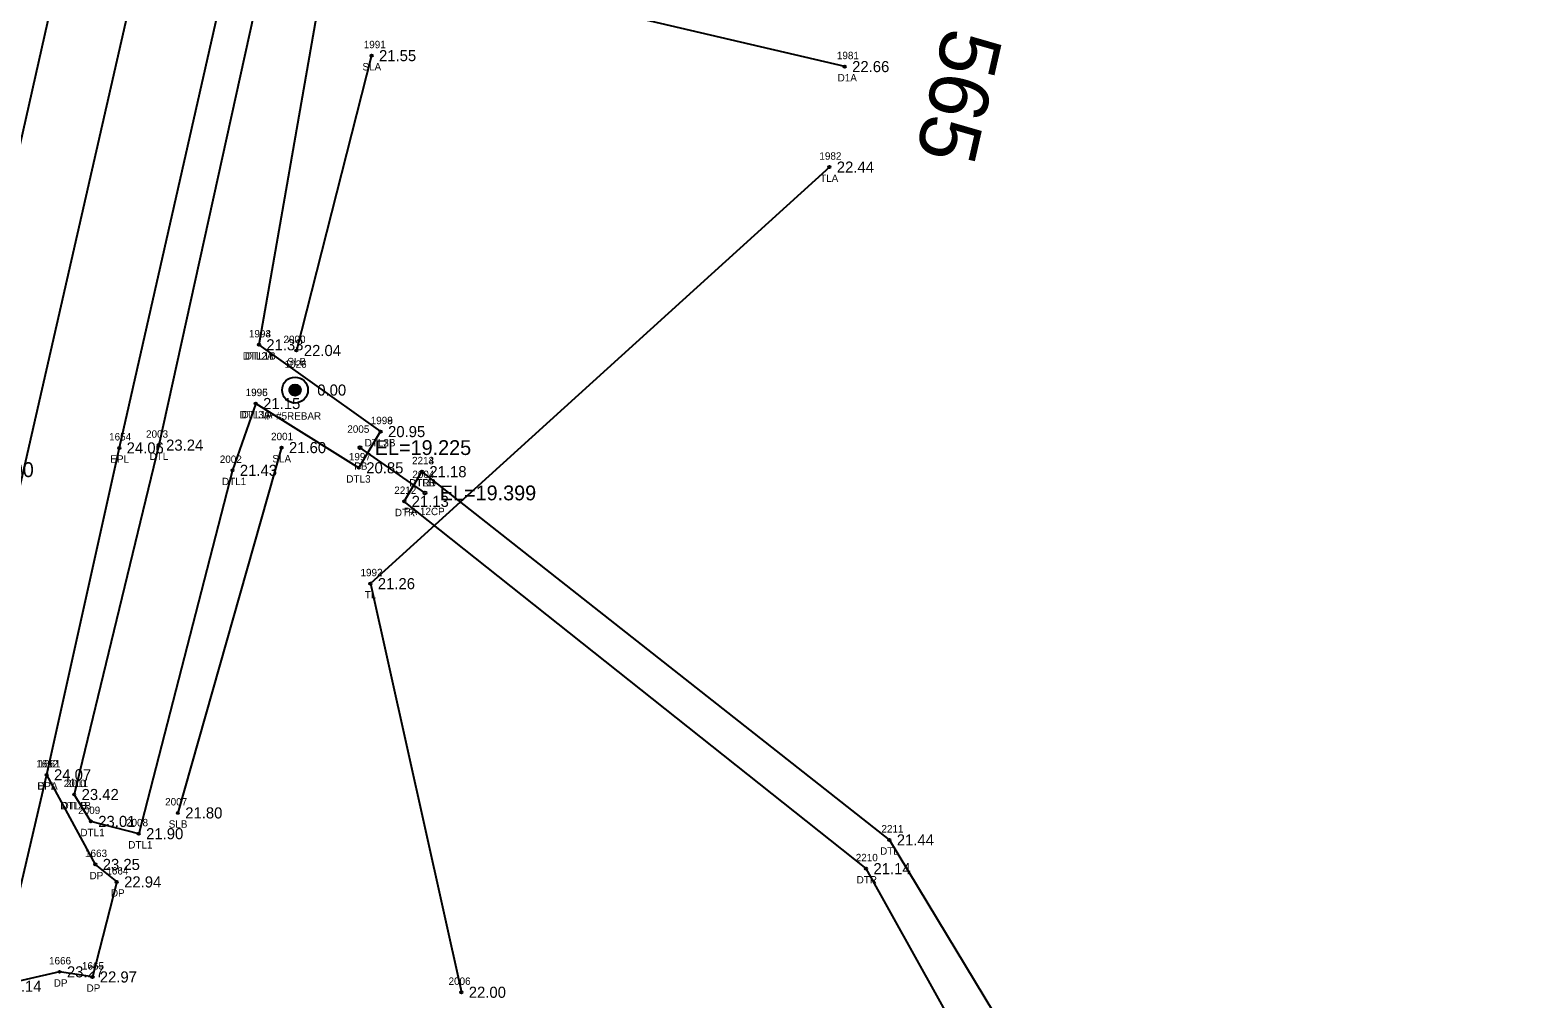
# Model space of a CAD drawing. Extents: x 2654414 to 2656963, y 761776 to 764965.
# Drawn here: x 2655506 to 2655709.5, y 762249.9 to 762380.7 of the extents above; entities that cross this region are included whole.
import ezdxf

# ---------------------------------------------------------------- set-up
doc = ezdxf.new("R2010")
doc.units = 0
for name, color, linetype in [('Default', 7, 'Continuous'), ('RD_EX_DR_Pipe', 7, 'Continuous'), ('RD_EX_DR_Pipe_txCode', 7, 'Continuous'), ('RD_EX_Driveway', 7, 'Continuous'), ('RD_EX_Driveway_txCode', 7, 'Continuous'), ('RD_EX_DV_Prop_txCode', 7, 'Continuous'), ('RD_EX_DV_PropPin', 7, 'Continuous'), ('RD_EX_H2O', 7, 'Continuous'), ('RD_EX_H2O_txCode', 7, 'Continuous'), ('RD_EX_Road', 7, 'Continuous'), ('RD_EX_Road_txCode', 7, 'Continuous'), ('RD_EX_TX_Driveway_ELEV', 7, 'Continuous'), ('RD_EX_TX_DV_Prop_ELEV', 7, 'Continuous'), ('RD_EX_TX_H2O_ELEV', 7, 'Continuous'), ('RD_EX_TX_Road_ELEV', 7, 'Continuous'), ('RD_EX_TX_VEG_ELEV', 7, 'Continuous'), ('RD_EX_VEG', 7, 'Continuous'), ('RD_EX_VEG_txCode', 7, 'Continuous'), ('RD_HC_Cl', 7, 'Continuous'), ('RD_HC_TX_Sta50', 7, 'Continuous'), ('RD_SMD_Locator', 7, 'Continuous'), ('RD_TX_Pipe_ElevEX', 7, 'Continuous')]:
    doc.layers.add(name, color=color, linetype=linetype)

msp = doc.modelspace()

# ---------------------------------------------------------------- linework, layer by layer
at = {"layer": 'Default'}
msp.add_line((2656050.51, 764712.37), (2655383.26, 761787.51), dxfattribs=at)
at = {"layer": 'RD_EX_DR_Pipe'}
msp.add_line((2655559.27, 762318.21), (2655550.49, 762324.33), dxfattribs=at)
at = {"layer": 'RD_EX_Driveway'}
for points in [[(2655615.95, 762375.77), (2655557.51, 762389.46), (2655538.99, 762389.2)], [(2655508.17, 762280.15), (2655514.75, 762268.05), (2655517.64, 762265.69), (2655514.35, 762252.86), (2655509.92, 762253.55), (2655501.46, 762251.6)]]:
    msp.add_lwpolyline(points, dxfattribs=at)
at = {"layer": 'RD_EX_DV_PropPin'}
for p, q in [((2655541.16, 762331.59), (2655541.16, 762332.62)), ((2655541.19, 762331.55), (2655541.19, 762332.65)), ((2655541.23, 762331.52), (2655541.23, 762332.68)), ((2655541.26, 762331.49), (2655541.26, 762332.71)), ((2655541.3, 762331.47), (2655541.3, 762332.73)), ((2655541.33, 762331.44), (2655541.33, 762332.76)), ((2655541.37, 762331.42), (2655541.37, 762332.78)), ((2655541.4, 762331.41), (2655541.4, 762332.79)), ((2655541.44, 762331.39), (2655541.44, 762332.81)), ((2655541.47, 762331.38), (2655541.47, 762332.82)), ((2655541.51, 762331.37), (2655541.51, 762332.83)), ((2655541.54, 762331.36), (2655541.54, 762332.84)), ((2655541.58, 762331.35), (2655541.58, 762332.85)), ((2655541.61, 762331.35), (2655541.61, 762332.85)), ((2655541.65, 762331.34), (2655541.65, 762332.86)), ((2655541.68, 762331.34), (2655541.68, 762332.86)), ((2655541.72, 762331.34), (2655541.72, 762332.86)), ((2655541.75, 762331.34), (2655541.75, 762332.86)), ((2655541.79, 762331.34), (2655541.79, 762332.86)), ((2655541.82, 762331.35), (2655541.82, 762332.85)), ((2655541.86, 762331.35), (2655541.86, 762332.85)), ((2655541.89, 762331.36), (2655541.89, 762332.84)), ((2655541.93, 762331.37), (2655541.93, 762332.83)), ((2655541.96, 762331.38), (2655541.96, 762332.82)), ((2655542, 762331.39), (2655542, 762332.81)), ((2655542.03, 762331.41), (2655542.03, 762332.79)), ((2655542.07, 762331.42), (2655542.07, 762332.78)), ((2655542.1, 762331.44), (2655542.1, 762332.76)), ((2655542.14, 762331.47), (2655542.14, 762332.73)), ((2655542.17, 762331.49), (2655542.17, 762332.71)), ((2655542.21, 762331.52), (2655542.21, 762332.68)), ((2655542.24, 762331.55), (2655542.24, 762332.65)), ((2655542.28, 762331.59), (2655542.28, 762332.62)), ((2655540.98, 762331.9), (2655540.98, 762332.3)), ((2655541.02, 762331.8), (2655541.02, 762332.4)), ((2655541.05, 762331.73), (2655541.05, 762332.47)), ((2655541.09, 762331.67), (2655541.09, 762332.53)), ((2655541.12, 762331.63), (2655541.12, 762332.57)), ((2655542.32, 762331.63), (2655542.32, 762332.57)), ((2655542.35, 762331.67), (2655542.35, 762332.53)), ((2655542.39, 762331.73), (2655542.39, 762332.47)), ((2655542.42, 762331.8), (2655542.42, 762332.4)), ((2655542.46, 762331.9), (2655542.46, 762332.3))]:
    msp.add_line(p, q, dxfattribs=at)
for radius in [1.75, 0.761]:
    msp.add_circle((2655541.72, 762332.1), radius, dxfattribs=at)
at = {"layer": 'RD_EX_H2O'}
for p, q in [((2655545.09, 762385.45), (2655536.84, 762338.21)), ((2655536.84, 762338.21), (2655553.28, 762326.49))]:
    msp.add_line(p, q, dxfattribs=at)
for points in [[(2655545.09, 762385.45), (2655540, 762387.21), (2655536.16, 762382.83), (2655523.31, 762324.66), (2655511.9, 762277.49)], [(2655536.41, 762330.28), (2655533.27, 762321.26), (2655520.61, 762272.2), (2655514.15, 762273.86), (2655511.9, 762277.49)], [(2655536.41, 762330.28), (2655550.34, 762321.6), (2655553.28, 762326.49)], [(2655458.25, 762004.65), (2655489.16, 762003.6), (2655538.42, 762005.59), (2655556.05, 762013.17), (2655587.88, 762051.39), (2655643.4, 762074.04), (2655655.85, 762091.76), (2655681.86, 762140.14), (2655683.72, 762146.53), (2655664.39, 762201.23), (2655621.98, 762271.36), (2655558.86, 762321.08)], [(2655459.71, 762010.57), (2655488.92, 762008.22), (2655537.08, 762011.25), (2655554.9, 762018.55), (2655583.72, 762054.68), (2655639.44, 762078.76), (2655651.66, 762094.07), (2655673.82, 762140.27), (2655676.22, 762150.22), (2655658.16, 762196.88), (2655618.83, 762267.48), (2655556.47, 762317.07), (2655558.86, 762321.08)]]:
    msp.add_lwpolyline(points, dxfattribs=at)
at = {"layer": 'RD_EX_Road'}
for points in [[(2655700.99, 763232.28), (2655693.55, 763198.57), (2655671.65, 763102.04), (2655649.04, 763001.06), (2655627.27, 762906.23), (2655605, 762809.37), (2655598.99, 762783.09), (2655583.65, 762714.14), (2655561.97, 762618.32), (2655556.36, 762593.84), (2655548.11, 762557.14), (2655540.1, 762522.48), (2655518.03, 762425.04), (2655496.48, 762329.56), (2655475.55, 762236.62), (2655473.2, 762226.14), (2655466.57, 762197.5), (2655460.06, 762168.16), (2655454.26, 762143.78), (2655432.5, 762049.88), (2655410.7, 761955.51), (2655388.17, 761858.43), (2655373.5, 761793.95)], [(2655670.04, 762995.18), (2655648.57, 762900.67), (2655631.27, 762824.03), (2655626.67, 762802.87), (2655621.78, 762781.91), (2655611.71, 762738.43), (2655604.93, 762708.62), (2655582.64, 762610.54), (2655576.46, 762583.32), (2655561.41, 762517.24), (2655539.15, 762414.81), (2655531.98, 762386.15), (2655517.98, 762324.29), (2655508.17, 762280.15), (2655501.46, 762251.6), (2655496.92, 762232.09), (2655477.2, 762144.97), (2655472.14, 762122.52), (2655453.74, 762045.1), (2655431.79, 761949.92), (2655409.76, 761853.25), (2655401.25, 761816.42), (2655394.61, 761787.37)]]:
    msp.add_lwpolyline(points, dxfattribs=at)
at = {"layer": 'RD_EX_VEG'}
for p, q in [((2655552.06, 762377.25), (2655541.91, 762337.44)), ((2655539.9, 762324.33), (2655525.89, 762275.01))]:
    msp.add_line(p, q, dxfattribs=at)
msp.add_lwpolyline([(2655613.88, 762362.2), (2655551.9, 762305.96), (2655564.18, 762250.79)], dxfattribs=at)
at = {"layer": 'RD_HC_Cl'}
msp.add_line((2656050.51, 764712.37), (2655383.26, 761787.51), dxfattribs=at)
at = {"layer": 'RD_SMD_Locator'}
for centre, radius in [((2655552.06, 762377.25), 0.15), ((2655615.95, 762375.77), 0.15), ((2655613.88, 762362.2), 0.15), ((2655536.84, 762338.21), 0.15), ((2655536.84, 762338.21), 0.15), ((2655541.91, 762337.44), 0.15), ((2655541.72, 762332.1), 0.15), ((2655536.41, 762330.28), 0.15), ((2655536.41, 762330.28), 0.15), ((2655553.28, 762326.49), 0.15), ((2655553.28, 762326.49), 0.15), ((2655523.31, 762324.66), 0.15), ((2655539.9, 762324.33), 0.15), ((2655550.49, 762324.33), 0.2), ((2655517.98, 762324.29), 0.15), ((2655533.27, 762321.26), 0.15), ((2655550.34, 762321.6), 0.15), ((2655558.86, 762321.08), 0.15), ((2655558.86, 762321.08), 0.15), ((2655559.27, 762318.21), 0.2), ((2655556.47, 762317.07), 0.15), ((2655551.9, 762305.96), 0.15), ((2655508.17, 762280.15), 0.15), ((2655508.17, 762280.15), 0.15), ((2655511.9, 762277.49), 0.15), ((2655511.9, 762277.49), 0.15), ((2655514.15, 762273.86), 0.15), ((2655525.89, 762275.01), 0.15), ((2655520.61, 762272.2), 0.15), ((2655621.98, 762271.36), 0.15), ((2655514.75, 762268.05), 0.15), ((2655618.83, 762267.48), 0.15), ((2655517.64, 762265.69), 0.15), ((2655509.92, 762253.55), 0.15), ((2655514.35, 762252.86), 0.15), ((2655564.18, 762250.79), 0.15)]:
    msp.add_circle(centre, radius, dxfattribs=at)

# ---------------------------------------------------------------- texts
at = {"layer": 'RD_EX_DR_Pipe_txCode'}
for s, p in [('2005', (2655548.78, 762326.33)), ('PB', (2655549.71, 762321.33)), ('2004', (2655557.56, 762320.21)), ('PA 12CP', (2655556.43, 762315.21))]:
    msp.add_text(s, height=1, dxfattribs=at).set_placement(p)
at = {"layer": 'RD_EX_Driveway_txCode'}
for s, p in [('1981', (2655614.89, 762376.77)), ('D1A', (2655614.99, 762373.77)), ('1662', (2655506.78, 762281.15)), ('DPA', (2655506.91, 762278.15)), ('1663', (2655513.36, 762269.05)), ('1664', (2655516.24, 762266.69)), ('DP', (2655513.97, 762266.05)), ('DP', (2655516.86, 762263.69)), ('1666', (2655508.5, 762254.55)), ('1665', (2655512.95, 762253.86)), ('DP', (2655509.14, 762251.55)), ('DP', (2655513.57, 762250.86))]:
    msp.add_text(s, height=1, dxfattribs=at).set_placement(p)
at = {"layer": 'RD_EX_DV_Prop_txCode'}
for s, p in [('1026', (2655540.31, 762335.1)), ('IP #5REBAR', (2655537.52, 762328.1))]:
    msp.add_text(s, height=1, dxfattribs=at).set_placement(p)
at = {"layer": 'RD_EX_H2O_txCode'}
for s, p in [('1993', (2655535.49, 762339.21)), ('1994', (2655535.49, 762339.21)), ('DTL2A', (2655534.66, 762336.21)), ('DTL1B', (2655534.95, 762336.21)), ('1996', (2655535.04, 762331.28)), ('1995', (2655535.06, 762331.28)), ('DTL3A', (2655534.22, 762328.28)), ('DTL1A', (2655534.51, 762328.28)), ('2003', (2655521.6, 762325.66)), ('1998', (2655551.94, 762327.49)), ('1999', (2655551.94, 762327.49)), ('DTL2B', (2655551.12, 762324.49)), ('DTL3B', (2655551.12, 762324.49)), ('DTL', (2655522.07, 762322.66)), ('2002', (2655531.56, 762322.26)), ('1997', (2655548.99, 762322.6)), ('2213', (2655557.52, 762322.08)), ('2214', (2655557.52, 762322.08)), ('DTL3', (2655548.65, 762319.6)), ('DTL1', (2655531.86, 762319.26)), ('2212', (2655555.12, 762318.07)), ('DTRB', (2655557.12, 762319.08)), ('DTLB', (2655557.15, 762319.08)), ('DTR', (2655555.2, 762315.07)), ('2010', (2655510.48, 762278.49)), ('2011', (2655510.8, 762278.49)), ('DTL1B', (2655510.02, 762275.49)), ('DTLB', (2655510.19, 762275.49)), ('2009', (2655512.44, 762274.86)), ('2008', (2655518.9, 762273.2)), ('DTL1', (2655512.74, 762271.86)), ('2211', (2655620.91, 762272.36)), ('DTL1', (2655519.2, 762270.2)), ('2210', (2655617.44, 762268.48)), ('DTL', (2655620.73, 762269.36)), ('DTR', (2655617.56, 762265.48))]:
    msp.add_text(s, height=1, dxfattribs=at).set_placement(p)
at = {"layer": 'RD_EX_Road_txCode'}
for s, p in [('1654', (2655516.61, 762325.29)), ('EPL', (2655516.78, 762322.29)), ('1661', (2655507.06, 762281.15)), ('EPL', (2655506.97, 762278.15))]:
    msp.add_text(s, height=1, dxfattribs=at).set_placement(p)
at = {"layer": 'RD_EX_TX_Driveway_ELEV'}
for s, p in [('22.66', (2655616.95, 762375.02)), ('24.07', (2655509.17, 762279.4)), ('23.25', (2655515.75, 762267.3)), ('22.94', (2655518.64, 762264.94)), ('23.27', (2655510.92, 762252.8)), ('22.97', (2655515.35, 762252.11)), ('24.14', (2655502.46, 762250.85))]:
    msp.add_text(s, height=1.5, dxfattribs=at).set_placement(p)
at = {"layer": 'RD_EX_TX_DV_Prop_ELEV'}
msp.add_text('0.00', height=1.5, dxfattribs=at).set_placement((2655544.72, 762331.35))
at = {"layer": 'RD_EX_TX_H2O_ELEV'}
for s, p in [('21.33', (2655537.84, 762337.46)), ('21.33', (2655537.84, 762337.46)), ('21.15', (2655537.41, 762329.53)), ('21.15', (2655537.41, 762329.53)), ('20.95', (2655554.28, 762325.74)), ('20.95', (2655554.28, 762325.74)), ('23.24', (2655524.31, 762323.91)), ('21.43', (2655534.27, 762320.51)), ('20.85', (2655551.34, 762320.85)), ('21.18', (2655559.86, 762320.33)), ('21.18', (2655559.86, 762320.33)), ('21.13', (2655557.47, 762316.32)), ('23.42', (2655512.9, 762276.74)), ('23.42', (2655512.9, 762276.74)), ('23.01', (2655515.15, 762273.11)), ('21.90', (2655521.61, 762271.45)), ('21.44', (2655622.98, 762270.61)), ('21.14', (2655619.83, 762266.73))]:
    msp.add_text(s, height=1.5, dxfattribs=at).set_placement(p)
at = {"layer": 'RD_EX_TX_Road_ELEV'}
for s, p in [('24.06', (2655518.98, 762323.54)), ('24.07', (2655509.17, 762279.4)), ('24.14', (2655502.46, 762250.85))]:
    msp.add_text(s, height=1.5, dxfattribs=at).set_placement(p)
at = {"layer": 'RD_EX_TX_VEG_ELEV'}
for s, p in [('21.55', (2655553.06, 762376.5)), ('22.44', (2655614.88, 762361.45)), ('22.04', (2655542.91, 762336.69)), ('21.60', (2655540.9, 762323.58)), ('21.26', (2655552.9, 762305.21)), ('21.80', (2655526.89, 762274.26)), ('22.00', (2655565.18, 762250.04))]:
    msp.add_text(s, height=1.5, dxfattribs=at).set_placement(p)
at = {"layer": 'RD_EX_VEG_txCode'}
for s, p in [('1991', (2655551, 762378.25)), ('SLA', (2655550.82, 762375.25)), ('1982', (2655612.53, 762363.2)), ('TLA', (2655612.62, 762360.2)), ('2000', (2655540.16, 762338.44)), ('SLB', (2655540.68, 762335.44)), ('2001', (2655538.48, 762325.33)), ('SLA', (2655538.66, 762322.33)), ('1992', (2655550.56, 762306.96)), ('TL', (2655551.13, 762303.96)), ('2007', (2655524.18, 762276.01)), ('SLB', (2655524.66, 762273.01)), ('2006', (2655562.45, 762251.79))]:
    msp.add_text(s, height=1, dxfattribs=at).set_placement(p)
at = {"layer": 'RD_HC_TX_Sta50'}
msp.add_text('565', height=8, rotation=257.149, dxfattribs=at).set_placement((2655629.5, 762381.32))
at = {"layer": 'RD_TX_Pipe_ElevEX'}
for s, p in [('EL=19.225', (2655552.49, 762323.33)), ('EL=0.000', (2655494.92, 762320.35)), ('EL=19.399', (2655561.27, 762317.21))]:
    msp.add_text(s, height=2, dxfattribs=at).set_placement(p)

doc.saveas('drawing.dxf')
